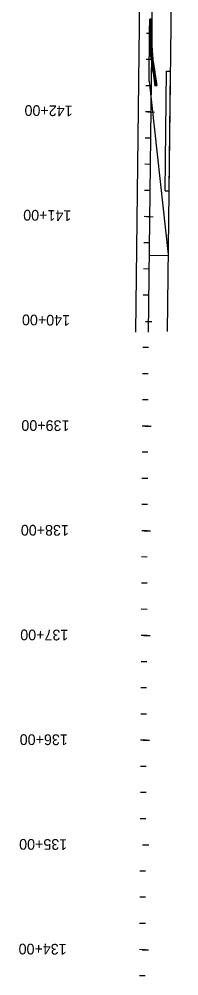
# Model space of a CAD drawing. Extents: x 17535628 to 17537899, y 7333852 to 7342653.
# Drawn here: x 17535640 to 17535792, y 7336058 to 7336972 of the extents above; entities that cross this region are included whole.
import ezdxf

# ---------------------------------------------------------------- set-up
doc = ezdxf.new("R2010")
doc.units = 0
for name, color, linetype in [('Default', 7, 'Continuous'), ('dsnCellElements', 7, 'Continuous'), ('dsnNonPlotable', 7, 'Continuous'), ('PavementMarking', 7, 'Continuous'), ('TextAlignmentLrg', 7, 'Continuous'), ('TextAlignmentSml', 7, 'Continuous')]:
    doc.layers.add(name, color=color, linetype=linetype)

msp = doc.modelspace()

# ---------------------------------------------------------------- linework, layer by layer
at = {"layer": 'Default'}
for p, q in [((17535779.15, 7336808.15), (17535780.47, 7336922.25)), ((17535780.47, 7336922.25), (17535784.47, 7336922.2)), ((17535783.15, 7336808.1), (17535784.47, 7336922.2)), ((17535779.15, 7336808.15), (17535783.15, 7336808.1))]:
    msp.add_line(p, q, dxfattribs=at)
at = {"layer": 'dsnCellElements'}
for p, q in [((17535764.45, 7336959.46), (17535764.62, 7336971.96)), ((17535766.49, 7336971.93), (17535764.62, 7336971.96)), ((17535765.05, 7336959.45), (17535765.22, 7336971.95)), ((17535765.72, 7336959.44), (17535765.89, 7336971.94)), ((17535766.32, 7336959.44), (17535766.49, 7336971.93)), ((17535764.44, 7336959.09), (17535766.32, 7336959.12)), ((17535764.44, 7336959.09), (17535764.69, 7336946.59)), ((17535766.32, 7336959.44), (17535764.45, 7336959.46)), ((17535765.04, 7336959.1), (17535765.29, 7336946.6)), ((17535765.72, 7336959.11), (17535765.96, 7336946.61)), ((17535766.32, 7336959.12), (17535766.56, 7336946.62)), ((17535764.69, 7336946.59), (17535766.56, 7336946.62)), ((17535764.7, 7336946.15), (17535766.57, 7336946.31)), ((17535764.7, 7336946.15), (17535765.75, 7336933.7)), ((17535765.3, 7336946.21), (17535766.35, 7336933.75)), ((17535765.97, 7336946.26), (17535767.02, 7336933.81)), ((17535766.57, 7336946.31), (17535767.62, 7336933.86)), ((17535765.75, 7336933.7), (17535767.62, 7336933.86)), ((17535765.79, 7336933.26), (17535767.65, 7336933.55)), ((17535765.79, 7336933.26), (17535767.67, 7336920.91)), ((17535766.38, 7336933.35), (17535768.26, 7336921)), ((17535767.05, 7336933.46), (17535768.93, 7336921.1)), ((17535767.65, 7336933.55), (17535769.52, 7336921.19)), ((17535767.67, 7336920.91), (17535769.52, 7336921.19)), ((17535767.71, 7336920.6), (17535769.57, 7336920.88)), ((17535768.31, 7336920.69), (17535770.18, 7336908.33)), ((17535768.97, 7336920.79), (17535770.85, 7336908.43)), ((17535769.57, 7336920.88), (17535771.44, 7336908.52)), ((17535767.71, 7336920.6), (17535769.59, 7336908.24)), ((17535769.59, 7336908.24), (17535771.44, 7336908.52))]:
    msp.add_line(p, q, dxfattribs=at)
at = {"layer": 'dsnNonPlotable'}
for p, q in [((17535751.42, 7336673.18), (17535762.19, 7337600.69)), ((17535763.42, 7336673.04), (17535774.19, 7337600.55)), ((17535781.61, 7336673.7), (17535792.37, 7337601.21))]:
    msp.add_line(p, q, dxfattribs=at)
at = {"layer": 'PavementMarking'}
for p, q in [((17535763.92, 7336912.87), (17535764.45, 7336959.46)), ((17535763.92, 7336912.83), (17535782.17, 7336747.05)), ((17535782.44, 7336746.08), (17535764.26, 7336746.3))]:
    msp.add_line(p, q, dxfattribs=at)
at = {"layer": 'TextAlignmentLrg'}
for p, q in [((17535765.91, 7336883.3), (17535760.45, 7336883.37)), ((17535764.69, 7336783.31), (17535759.23, 7336783.37)), ((17535760.4, 7336683.35), (17535766.52, 7336683.28)), ((17535762.91, 7336583.31), (17535757.45, 7336583.34)), ((17535762.38, 7336483.32), (17535756.92, 7336483.35)), ((17535761.85, 7336383.32), (17535756.39, 7336383.35)), ((17535761.32, 7336283.32), (17535755.86, 7336283.35)), ((17535757.73, 7336183.34), (17535763.85, 7336183.3)), ((17535760.25, 7336083.32), (17535754.79, 7336083.35))]:
    msp.add_line(p, q, dxfattribs=at)
at = {"layer": 'TextAlignmentSml'}
for p, q in [((17535766.83, 7336958.29), (17535761.37, 7336958.36)), ((17535766.53, 7336933.29), (17535761.07, 7336933.36)), ((17535766.22, 7336908.3), (17535760.76, 7336908.36)), ((17535762.85, 7336883.34), (17535768.97, 7336883.26)), ((17535765.61, 7336858.3), (17535760.15, 7336858.37)), ((17535765.3, 7336833.3), (17535759.84, 7336833.37)), ((17535764.99, 7336808.3), (17535759.53, 7336808.37)), ((17535761.63, 7336783.34), (17535767.75, 7336783.27)), ((17535764.38, 7336758.31), (17535758.92, 7336758.37)), ((17535764.07, 7336733.31), (17535758.61, 7336733.38)), ((17535763.77, 7336708.31), (17535758.31, 7336708.38)), ((17535760.4, 7336683.35), (17535766.52, 7336683.28)), ((17535763.31, 7336658.31), (17535757.85, 7336658.34)), ((17535763.17, 7336633.31), (17535757.71, 7336633.34)), ((17535763.04, 7336608.31), (17535757.58, 7336608.34)), ((17535759.85, 7336583.33), (17535765.97, 7336583.3)), ((17535762.78, 7336558.32), (17535757.32, 7336558.34)), ((17535762.64, 7336533.32), (17535757.18, 7336533.34)), ((17535762.51, 7336508.32), (17535757.05, 7336508.34)), ((17535759.32, 7336483.33), (17535765.44, 7336483.3)), ((17535762.25, 7336458.32), (17535756.79, 7336458.35)), ((17535762.11, 7336433.32), (17535756.65, 7336433.35)), ((17535761.98, 7336408.32), (17535756.52, 7336408.35)), ((17535758.79, 7336383.33), (17535764.91, 7336383.3)), ((17535761.71, 7336358.32), (17535756.25, 7336358.35)), ((17535761.58, 7336333.32), (17535756.12, 7336333.35)), ((17535761.45, 7336308.32), (17535755.99, 7336308.35)), ((17535758.26, 7336283.34), (17535764.38, 7336283.3)), ((17535761.18, 7336258.32), (17535755.72, 7336258.35)), ((17535761.05, 7336233.32), (17535755.59, 7336233.35)), ((17535760.92, 7336208.32), (17535755.46, 7336208.35)), ((17535757.73, 7336183.34), (17535763.85, 7336183.3)), ((17535760.65, 7336158.32), (17535755.19, 7336158.35)), ((17535760.52, 7336133.32), (17535755.06, 7336133.35)), ((17535760.39, 7336108.32), (17535754.93, 7336108.35)), ((17535757.19, 7336083.34), (17535763.31, 7336083.31)), ((17535760.12, 7336058.32), (17535754.66, 7336058.35))]:
    msp.add_line(p, q, dxfattribs=at)

# ---------------------------------------------------------------- texts
at = {"layer": 'TextAlignmentLrg'}
for s, rotation, p in [('140+00', 179.29715, (17535688.53, 7336689.33)), ('135+00', 179.69587, (17535685.81, 7336188.82))]:
    msp.add_text(s, height=10.2, rotation=rotation, dxfattribs=at).set_placement(p)
at = {"layer": 'TextAlignmentSml'}
for s, rotation, p in [('142+00', 179.29715, (17535690.98, 7336889.32)), ('141+00', 179.29715, (17535689.75, 7336789.33)), ('140+00', 179.29715, (17535688.53, 7336689.33)), ('139+00', 179.69587, (17535687.94, 7336588.81)), ('138+00', 179.69587, (17535687.41, 7336488.81)), ('137+00', 179.69587, (17535686.88, 7336388.82)), ('136+00', 179.69587, (17535686.34, 7336288.82)), ('135+00', 179.69587, (17535685.81, 7336188.82)), ('134+00', 179.69587, (17535685.28, 7336088.82))]:
    msp.add_text(s, height=10.2, rotation=rotation, dxfattribs=at).set_placement(p)

doc.saveas('drawing.dxf')
